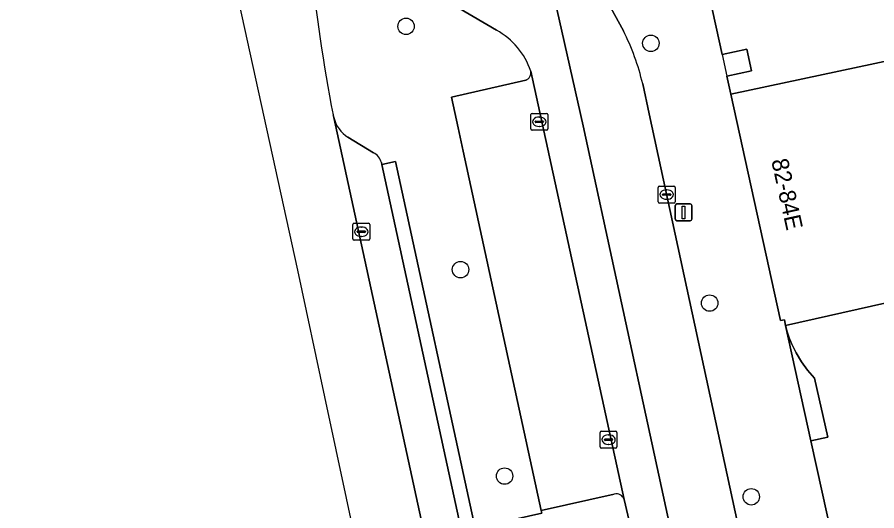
# Model space of a CAD drawing. Extents: x 160554 to 161248, y 385329 to 386506.
# Drawn here: x 160716 to 160767.1, y 385829.7 to 385859.1 of the extents above; entities that cross this region are included whole.
import ezdxf

# ---------------------------------------------------------------- set-up
doc = ezdxf.new("R2010")
doc.units = 0
for name, color, linetype in [('IMGEO_Berm_groen', 7, 'Continuous'), ('IMGEO_Boom', 7, 'Continuous'), ('IMGEO_Erf', 7, 'Continuous'), ('IMGEO_Fietspad_gesloten', 7, 'Continuous'), ('IMGEO_Kolk', 7, 'Continuous'), ('IMGEO_Lichtmast', 7, 'Continuous'), ('IMGEO_Pand', 7, 'Continuous'), ('IMGEO_Pand_nummerreeks', 7, 'Continuous'), ('IMGEO_Pand_overbouw', 7, 'Continuous'), ('IMGEO_Parkeervlak_open', 7, 'Continuous'), ('IMGEO_Rijbaan_lokaal_gesloten', 7, 'Continuous'), ('IMGEO_Voetpad_open', 7, 'Continuous')]:
    doc.layers.add(name, color=color, linetype=linetype)

msp = doc.modelspace()

# ---------------------------------------------------------------- linework, layer by layer
at = {"layer": 'IMGEO_Berm_groen'}
for points in [[(160744.49, 385858.341), (160734.067, 385864.463)], [(160742.513, 385851.153), (160742.213, 385852.528), (160741.815, 385854.355), (160746.236, 385855.367)], [(160734.78, 385853.307), (160734.816, 385853.141)], [(160735.664, 385851.975), (160737.173, 385851.055)], [(160737.654, 385850.466), (160737.667, 385850.35), (160738.499, 385850.527), (160743.233, 385828.714), (160747.193, 385829.613), (160747.16, 385829.766), (160742.513, 385851.153)]]:
    msp.add_lwpolyline(points, dxfattribs=at)
for centre, radius, start, end in [((160828.417, 385871.536), 95.395, 185.49799, 191.0163), ((160742.446, 385854.54), 4.315, 18.4767, 61.7295), ((160746.043, 385855.83), 0.502, 292.5904, 8.9055), ((160736.73, 385853.642), 1.978, 194.6575, 237.3972), ((160736.76, 385850.227), 0.925, 14.9657, 63.5071)]:
    msp.add_arc(centre, radius, start, end, dxfattribs=at)
at = {"layer": 'IMGEO_Boom'}
for centre in [(160739.118, 385858.569), (160753.68, 385857.563), (160742.358, 385844.098), (160757.177, 385842.106), (160744.979, 385831.813), (160759.653, 385830.583)]:
    msp.add_circle(centre, 0.489, dxfattribs=at)
at = {"layer": 'IMGEO_Erf'}
msp.add_lwpolyline([(160761.698, 385840.764), (160763.205, 385833.915), (160764.197, 385834.133), (160763.423, 385837.649), (160763.006, 385838.109), (160762.635, 385838.607), (160762.314, 385839.138), (160762.044, 385839.697), (160761.908, 385840.046), (160761.794, 385840.4)], close=True, dxfattribs=at)
at = {"layer": 'IMGEO_Fietspad_gesloten'}
for points in [[(160743.874, 385877.244), (160746.687, 385864.512), (160746.978, 385864.559), (160749.654, 385852.647), (160775.118, 385735.103), (160775.148, 385734.947), (160779.078, 385735.819), (160768.677, 385783.529), (160753.582, 385853.359)], [(160752.047, 385858.308), (160751.082, 385860.062), (160750.213, 385862.278), (160747.348, 385875.432)], [(160753.582, 385853.359), (160753.194, 385855.146)]]:
    msp.add_lwpolyline(points, dxfattribs=at)
msp.add_arc((160739.597, 385852.003), 13.955, 13.0162, 26.8598, dxfattribs=at)
at = {"layer": 'IMGEO_Kolk'}
for p, q in [((160746.543, 385852.469), (160746.543, 385853.321)), ((160746.618, 385853.395), (160747.47, 385853.395)), ((160747.031, 385853.175), (160747.056, 385853.175)), ((160747.544, 385853.321), (160747.544, 385852.469)), ((160746.802, 385852.889), (160746.802, 385852.901)), ((160747.24, 385852.852), (160746.842, 385852.852)), ((160746.845, 385852.938), (160747.243, 385852.938)), ((160747.286, 385852.901), (160747.286, 385852.889)), ((160747.47, 385852.395), (160746.618, 385852.395)), ((160747.054, 385852.615), (160747.029, 385852.615)), ((160754.193, 385849.061), (160755.045, 385849.061)), ((160754.118, 385848.135), (160754.118, 385848.987)), ((160754.377, 385848.555), (160754.377, 385848.567)), ((160754.42, 385848.604), (160754.818, 385848.604)), ((160754.606, 385848.841), (160754.631, 385848.841)), ((160754.861, 385848.567), (160754.861, 385848.555)), ((160755.119, 385848.987), (160755.119, 385848.135)), ((160755.045, 385848.061), (160754.193, 385848.061)), ((160754.815, 385848.518), (160754.417, 385848.518)), ((160754.629, 385848.281), (160754.604, 385848.281)), ((160735.957, 385845.927), (160735.957, 385846.779)), ((160736.032, 385846.853), (160736.884, 385846.853)), ((160736.445, 385846.633), (160736.47, 385846.633)), ((160736.958, 385846.779), (160736.958, 385845.927)), ((160736.216, 385846.347), (160736.216, 385846.359)), ((160736.654, 385846.31), (160736.256, 385846.31)), ((160736.259, 385846.396), (160736.657, 385846.396)), ((160736.468, 385846.073), (160736.443, 385846.073)), ((160736.7, 385846.359), (160736.7, 385846.347)), ((160736.884, 385845.853), (160736.032, 385845.853)), ((160750.662, 385833.555), (160750.662, 385834.407)), ((160750.737, 385834.481), (160751.589, 385834.481)), ((160751.15, 385834.261), (160751.175, 385834.261)), ((160751.663, 385834.407), (160751.663, 385833.555)), ((160750.921, 385833.975), (160750.921, 385833.987)), ((160751.359, 385833.938), (160750.961, 385833.938)), ((160750.964, 385834.024), (160751.362, 385834.024)), ((160751.405, 385833.987), (160751.405, 385833.975)), ((160751.589, 385833.481), (160750.737, 385833.481)), ((160751.173, 385833.701), (160751.148, 385833.701))]:
    msp.add_line(p, q, dxfattribs=at)
for points in [[(160746.543, 385852.469), (160746.543, 385853.321)], [(160746.618, 385853.395), (160747.47, 385853.395)], [(160747.544, 385853.321), (160747.544, 385852.469)], [(160747.47, 385852.395), (160746.618, 385852.395)], [(160754.193, 385849.061), (160755.045, 385849.061)], [(160754.118, 385848.135), (160754.118, 385848.987)], [(160755.119, 385848.987), (160755.119, 385848.135)], [(160755.045, 385848.061), (160754.193, 385848.061)], [(160735.957, 385845.927), (160735.957, 385846.779)], [(160736.032, 385846.853), (160736.884, 385846.853)], [(160736.958, 385846.779), (160736.958, 385845.927)], [(160736.884, 385845.853), (160736.032, 385845.853)], [(160750.662, 385833.555), (160750.662, 385834.407)], [(160750.737, 385834.481), (160751.589, 385834.481)], [(160751.663, 385834.407), (160751.663, 385833.555)], [(160751.589, 385833.481), (160750.737, 385833.481)]]:
    msp.add_lwpolyline(points, dxfattribs=at)
for centre, radius, start, end in [((160746.62, 385853.319), 0.0765, 91.552, 178.448), ((160746.62, 385853.319), 0.0765, 91.552, 178.448), ((160747.468, 385853.319), 0.0765, 1.552, 88.448), ((160747.468, 385853.319), 0.0765, 1.552, 88.448), ((160746.842, 385852.898), 0.0403, 85.8775, 175.7526), ((160746.839, 385852.888), 0.0366, 178.938, 274.7102), ((160747.243, 385852.895), 0.043, 264.8664, 352.4533), ((160747.247, 385852.9), 0.0386, 1.7309, 96.639), ((160746.62, 385852.471), 0.0765, 181.552, 268.448), ((160746.62, 385852.471), 0.0765, 181.552, 268.448), ((160747.468, 385852.471), 0.0765, 271.552, 358.448), ((160747.468, 385852.471), 0.0765, 271.552, 358.448), ((160754.195, 385848.985), 0.0765, 91.552, 178.448), ((160754.195, 385848.985), 0.0765, 91.552, 178.448), ((160755.043, 385848.985), 0.0765, 1.552, 88.448), ((160755.043, 385848.985), 0.0765, 1.552, 88.448), ((160754.417, 385848.564), 0.0403, 85.8775, 175.7526), ((160754.414, 385848.554), 0.0366, 178.938, 274.7102), ((160754.818, 385848.561), 0.043, 264.8664, 352.4533), ((160754.822, 385848.566), 0.0386, 1.7309, 96.639), ((160754.195, 385848.137), 0.0765, 181.552, 268.448), ((160754.195, 385848.137), 0.0765, 181.552, 268.448), ((160755.043, 385848.137), 0.0765, 271.552, 358.448), ((160755.043, 385848.137), 0.0765, 271.552, 358.448), ((160736.034, 385846.777), 0.0765, 91.552, 178.448), ((160736.034, 385846.777), 0.0765, 91.552, 178.448), ((160736.882, 385846.777), 0.0765, 1.552, 88.448), ((160736.882, 385846.777), 0.0765, 1.552, 88.448), ((160736.256, 385846.356), 0.0403, 85.8775, 175.7526), ((160736.253, 385846.346), 0.0366, 178.938, 274.7102), ((160736.657, 385846.353), 0.043, 264.8664, 352.4533), ((160736.661, 385846.358), 0.0386, 1.7309, 96.639), ((160736.034, 385845.929), 0.0765, 181.552, 268.448), ((160736.034, 385845.929), 0.0765, 181.552, 268.448), ((160736.882, 385845.929), 0.0765, 271.552, 358.448), ((160736.882, 385845.929), 0.0765, 271.552, 358.448), ((160750.739, 385834.405), 0.0765, 91.552, 178.448), ((160750.739, 385834.405), 0.0765, 91.552, 178.448), ((160751.587, 385834.405), 0.0765, 1.552, 88.448), ((160751.587, 385834.405), 0.0765, 1.552, 88.448), ((160750.961, 385833.984), 0.0403, 85.8775, 175.7526), ((160750.958, 385833.974), 0.0366, 178.938, 274.7102), ((160751.362, 385833.981), 0.043, 264.8664, 352.4533), ((160751.366, 385833.986), 0.0386, 1.7309, 96.639), ((160750.739, 385833.557), 0.0765, 181.552, 268.448), ((160750.739, 385833.557), 0.0765, 181.552, 268.448), ((160751.587, 385833.557), 0.0765, 271.552, 358.448), ((160751.587, 385833.557), 0.0765, 271.552, 358.448)]:
    msp.add_arc(centre, radius, start, end, dxfattribs=at)
for centre, major_axis, ratio, start_param, end_param in [((160747.03, 385852.895), (-0.387, 0.002), 0.722429, 4.712389, 7.853982), ((160747.055, 385852.895), (-0.39, 0.002), 0.717154, 1.570796, 4.712389), ((160754.605, 385848.561), (-0.387, 0.002), 0.722429, 4.712389, 7.853982), ((160754.63, 385848.561), (-0.39, 0.002), 0.717154, 1.570796, 4.712389), ((160736.444, 385846.353), (-0.387, 0.002), 0.722429, 4.712389, 7.853982), ((160736.469, 385846.353), (-0.39, 0.002), 0.717154, 1.570796, 4.712389), ((160751.149, 385833.981), (-0.387, 0.002), 0.722429, 4.712389, 7.853982), ((160751.174, 385833.981), (-0.39, 0.002), 0.717154, 1.570796, 4.712389)]:
    msp.add_ellipse(centre, major_axis=major_axis, ratio=ratio, start_param=start_param, end_param=end_param, dxfattribs=at)
at = {"layer": 'IMGEO_Lichtmast'}
for p, q in [((160755.127, 385847.103), (160755.127, 385847.903)), ((160755.127, 385847.903), (160755.127, 385847.103)), ((160755.227, 385848.003), (160756.017, 385848.003)), ((160756.017, 385848.003), (160755.227, 385848.003)), ((160756.117, 385847.903), (160756.117, 385847.103)), ((160756.117, 385847.103), (160756.117, 385847.903)), ((160756.017, 385847.003), (160755.227, 385847.003)), ((160755.227, 385847.003), (160756.017, 385847.003))]:
    msp.add_line(p, q, dxfattribs=at)
msp.add_lwpolyline([(160755.547, 385847.878), (160755.697, 385847.878), (160755.697, 385847.128), (160755.547, 385847.128), (160755.547, 385847.878)], dxfattribs=at)
for centre, start, end in [((160755.227, 385847.903), 90, 180), ((160755.227, 385847.903), 90, 180), ((160756.017, 385847.903), 0, 90), ((160756.017, 385847.903), 360, 90), ((160755.227, 385847.103), 180, 270), ((160755.227, 385847.103), 180, 270), ((160756.017, 385847.103), 270, 0), ((160756.017, 385847.103), 270, 0)]:
    msp.add_arc(centre, 0.1, start, end, dxfattribs=at)
at = {"layer": 'IMGEO_Pand'}
for points in [[(160777.279, 385870.849), (160758.975, 385867.079), (160755.843, 385866.393), (160757.924, 385856.888), (160759.385, 385857.208), (160759.667, 385855.919), (160758.206, 385855.6), (160758.439, 385854.537), (160779.843, 385859.099)], [(160788.241, 385854.277), (160785.345, 385853.643), (160785.461, 385853.115), (160781.346, 385852.214), (160779.843, 385859.099), (160758.439, 385854.537), (160761.387, 385841.069), (160761.62, 385841.119), (160761.698, 385840.764), (160789.816, 385847.106), (160789.778, 385847.261)], [(160797.582, 385839.533), (160795.644, 385848.382), (160795.61, 385848.538), (160789.778, 385847.261), (160789.816, 385847.106), (160761.698, 385840.764), (160761.794, 385840.4), (160761.908, 385840.046), (160762.044, 385839.697), (160762.314, 385839.138), (160762.635, 385838.607), (160763.006, 385838.109), (160763.423, 385837.649), (160764.197, 385834.133), (160763.205, 385833.915), (160766.446, 385819.186), (160766.088, 385819.108), (160767.998, 385810.411), (160782.162, 385813.51), (160777.43, 385835.122)]]:
    msp.add_lwpolyline(points, close=True, dxfattribs=at)
at = {"layer": 'IMGEO_Pand_overbouw'}
for points in [[(160758.206, 385855.6), (160759.667, 385855.919), (160759.385, 385857.208), (160757.924, 385856.888)], [(160763.205, 385833.915), (160764.197, 385834.133), (160763.423, 385837.649), (160763.006, 385838.109), (160762.635, 385838.607), (160762.314, 385839.138), (160762.044, 385839.697), (160761.908, 385840.046), (160761.794, 385840.4), (160761.698, 385840.764)]]:
    msp.add_lwpolyline(points, close=True, dxfattribs=at)
at = {"layer": 'IMGEO_Parkeervlak_open'}
for points in [[(160752.087, 385830.426), (160746.539, 385855.908)], [(160746.236, 385855.367), (160741.815, 385854.355), (160742.213, 385852.528), (160742.513, 385851.153), (160747.16, 385829.766), (160751.504, 385830.745)], [(160734.816, 385853.141), (160740.309, 385827.873), (160742.46, 385828.352), (160737.667, 385850.35), (160737.654, 385850.466)], [(160737.173, 385851.055), (160735.664, 385851.975)]]:
    msp.add_lwpolyline(points, dxfattribs=at)
for centre, radius, start, end in [((160746.043, 385855.83), 0.502, 292.5904, 8.9055), ((160736.73, 385853.642), 1.978, 194.6575, 237.3972), ((160736.76, 385850.227), 0.925, 14.9657, 63.5071), ((160751.628, 385830.279), 0.482, 17.7799, 104.8478)]:
    msp.add_arc(centre, radius, start, end, dxfattribs=at)
at = {"layer": 'IMGEO_Rijbaan_lokaal_gesloten'}
for points in [[(160715.986, 385920.097), (160719.827, 385902.586), (160732.663, 385844.066), (160734.272, 385836.538), (160774.456, 385648.538), (160783.981, 385603.977), (160786.986, 385589.919), (160802.685, 385519.246), (160829.424, 385398.876), (160836.967, 385359.152), (160838.712, 385333.406), (160857.818, 385334.076)], [(160760.316, 385735.594), (160755.198, 385759.167), (160740.682, 385826.157), (160740.309, 385827.873), (160734.816, 385853.141), (160734.78, 385853.307)]]:
    msp.add_lwpolyline(points, dxfattribs=at)
msp.add_arc((160828.417, 385871.536), 95.395, 185.49799, 191.0163, dxfattribs=at)
at = {"layer": 'IMGEO_Voetpad_open'}
for points in [[(160781.262, 385750), (160780.116, 385755.219), (160777.992, 385764.891), (160774.791, 385779.47), (160772.013, 385792.125), (160769.9, 385801.747), (160767.998, 385810.411), (160766.088, 385819.108), (160766.446, 385819.186), (160763.205, 385833.915), (160761.698, 385840.764), (160761.62, 385841.119), (160761.387, 385841.069), (160758.439, 385854.537), (160758.206, 385855.6), (160759.667, 385855.919), (160759.385, 385857.208), (160757.924, 385856.888), (160755.843, 385866.393), (160749.452, 385895.585), (160748.25, 385902.591), (160746.075, 385901.918), (160737.558, 385899.319), (160737.091, 385899.177)], [(160747.348, 385875.432), (160750.213, 385862.278), (160751.082, 385860.062), (160752.047, 385858.308)], [(160734.067, 385864.463), (160744.49, 385858.341)], [(160775.118, 385735.103), (160749.654, 385852.647), (160746.978, 385864.559), (160746.687, 385864.512), (160746.74, 385864.272)], [(160746.539, 385855.908), (160752.087, 385830.426), (160752.445, 385828.891), (160758.99, 385798.701), (160759.334, 385797.113), (160767.479, 385759.49), (160767.797, 385758.002), (160772.672, 385735.471), (160773.926, 385735.754)], [(160753.194, 385855.146), (160753.582, 385853.359), (160768.677, 385783.529), (160779.078, 385735.819), (160779.287, 385734.864)], [(160766.892, 385759.829), (160762.526, 385758.857), (160762.559, 385758.704), (160758.619, 385757.857), (160750.573, 385794.958), (160750.11, 385797.017), (160743.679, 385826.657), (160743.233, 385828.714), (160738.499, 385850.527), (160737.667, 385850.35), (160742.46, 385828.352), (160742.843, 385826.594), (160756.782, 385762.497)], [(160751.504, 385830.745), (160747.16, 385829.766), (160747.193, 385829.613), (160743.233, 385828.714), (160743.679, 385826.657), (160747.646, 385827.566), (160747.68, 385827.413), (160752.051, 385828.391)], [(160752.445, 385828.891), (160752.087, 385830.426)]]:
    msp.add_lwpolyline(points, dxfattribs=at)
for centre, radius, start, end in [((160742.446, 385854.54), 4.315, 18.4767, 61.7295), ((160739.597, 385852.003), 13.955, 13.0162, 26.8598), ((160751.628, 385830.279), 0.482, 17.7799, 104.8478)]:
    msp.add_arc(centre, radius, start, end, dxfattribs=at)

# ---------------------------------------------------------------- texts
at = {"layer": 'IMGEO_Pand_nummerreeks'}
msp.add_text('82-84E', height=1, rotation=282.347, dxfattribs=at).set_placement((160760.839, 385850.59))

doc.saveas('drawing.dxf')
